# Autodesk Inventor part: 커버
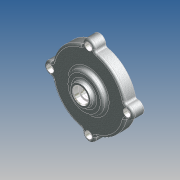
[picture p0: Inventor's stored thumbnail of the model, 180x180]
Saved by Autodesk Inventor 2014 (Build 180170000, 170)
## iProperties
Created: 2012-05
Part Number: 커버
Document SubType Name: 모델링
Designer: SeoGD™
Material: 알루미늄 6061
Mass: 196.657 g
Surface Area: 278.607 cm^2
Volume: 72.5671 cm^3
Density: 2.71 g/cm^3
Appearance: 알루미늄 캐스트
변환 표준: STEP AP214IS
파일 이름: C:\Users\SeoGD\Desktop\?쒗뿕\而ㅻ쾭-1.stp
전처리기: Build: 253, Release: 2010 SP1 - Date: Wed 07/29/2009
전송 단위: 밀리미터
불확실성: 0.01
Author: SeoGD™
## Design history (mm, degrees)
sketch "스케치1"
  geometry: L1 (0, 0)-(0, 26); L2 (50, 0)-(50, 15); L3 (50, 15)-(25, 15); L4 (25, 15)-(25, 21); L5 (25, 21)-(15, 21); L6 (15, 21)-(13.66, 26); L7 (13.66, 26)-(10, 26); L8 (50, 0)-(45, 0); L9 (45, 0)-(45, 10); L10 (45, 10)-(14.5, 10); L11 (14.5, 10)-(13.266, 3); L12 (13.266, 3)-(11, 3); L13 (11, 3)-(11, 16); L14 (11, 16)-(7.5, 16); L15 (7.5, 16)-(7.5, 19); L16 (7.5, 19)-(10, 19); L17 (10, 19)-(10, 26)
  constraints: 34 end point, 10 parallel, 2 perpendicular, 2 point on line, 1 vertical
  dimensions: "d11" = 100 diameter of L2 L1; "d12" = 22 diameter of L13 L1; "d13" = 90 diameter of L9 L1; "d14" = 15 distance between parallel lines of L3 L8; "d15" = 10 distance between parallel lines of L8 L10; "d16" = 29 diameter of L10.end L1; "d17" = 100 deg angle of L11 L10; "d18" = 7 distance between parallel lines of L12 L10; "d19" = 13 distance between parallel lines of L14 L12; "d20" = 3 distance between parallel lines of L16 L14; "d21" = 15 diameter of L15 L1; "d22" = 20 diameter of L17 L1; "d23" = 30 diameter of L5.end L1; "d24" = 6 distance between parallel lines of L5 L3; "d25" = 50 diameter of L4 L1; "d26" = 105 deg angle of L5 L6; "d50" = 26 distance of L1.start L1.end
revolve "회전1" sketch "스케치1" stored, may be unused: angle "d27" = 90 deg
sketch "스케치2" dims "d29" = 104
  geometry: A1 r 8.5 centre (0, 52) between (8.074, 49.344) and (-8.074, 49.344); A2 r 50 centre (0, 0) between (-8.074, 49.344) and (8.074, 49.344) reference; 2 further points
  constraints: 4 point on circle, 2 vertical alignment, 1 centre point, 1 coincident, 2 other
  dimensions: "d28" = 17 diameter of A1
extrude "돌출1" join sketch "스케치2" stored distance "d30" = 10; taper "d31" = 0 deg
fillet "모깎기3" dims "d32" = 3
fillet "모깎기4" dims "d45" = 3, "d46" = 0.2
chamfer "모따기1" distance "d47" = 1; stored, may be unused: second distance "d48" = 2, angle "d49" = 45 deg
hole "구멍2" diameter "d38" = 5.5; stored, may be unused: countersink angle "d42" = 90 deg, drill point angle "d44" = 118 deg; dims "d36" = 10, "d37" = 10, "d39" = 6, "d40" = 9.5, "d41" = 5.4, "d43" = 8
node "솔리드1"
node "솔리드 본체"
node "곡면 본체"
pattern_circular "원형 패턴1" dims angle "d34" = 360 deg
pattern_circular "원형 패턴2" dims angle "d52" = 360 deg
node "솔리드2"
